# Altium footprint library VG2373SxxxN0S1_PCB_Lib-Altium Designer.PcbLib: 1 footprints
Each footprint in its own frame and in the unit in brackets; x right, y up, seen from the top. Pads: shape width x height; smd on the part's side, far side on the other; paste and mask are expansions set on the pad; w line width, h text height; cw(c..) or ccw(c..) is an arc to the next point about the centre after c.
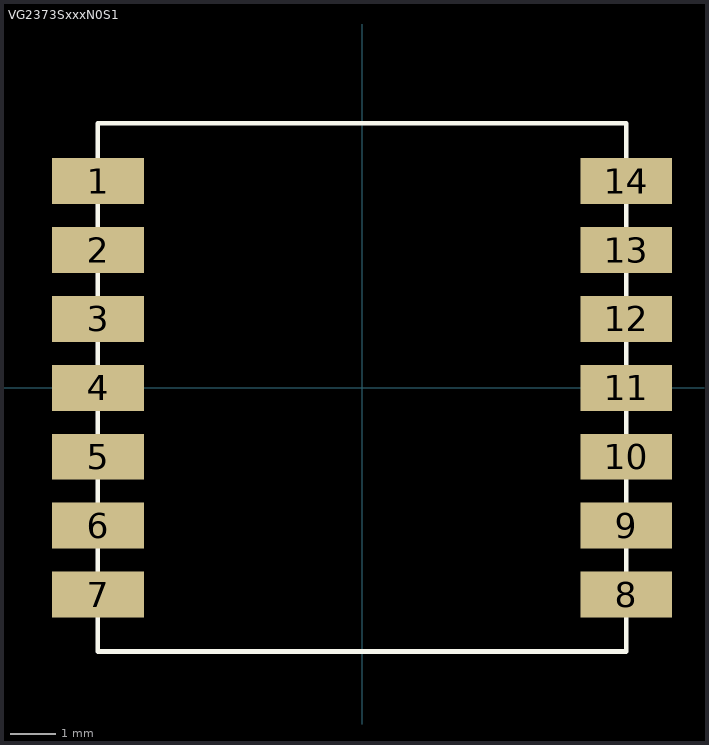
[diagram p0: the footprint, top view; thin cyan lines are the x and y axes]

## VG2373SxxxN0S1 [mm]
pads (15):
  round 1 on Top Overlay: 1(-6.604,5.842)
  rect 2x1 smd: 1(-5.75,4.5) 2(-5.75,3) 3(-5.75,1.5) 4(-5.75,0) 5(-5.75,-1.5) 6(-5.75,-3) 7(-5.75,-4.5) 8(5.75,-4.5) 9(5.75,-3) 10(5.75,-1.5) 11(5.75,0) 12(5.75,1.5) 13(5.75,3) 14(5.75,4.5)
Top Overlay:
  lines w0.1: -5.752,-5.74 5.748,-5.74 5.748,5.76 -5.752,5.76 -5.752,-5.74
3D body: height 1, standoff 0, extent -5.752,-5.74 5.75,5.76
